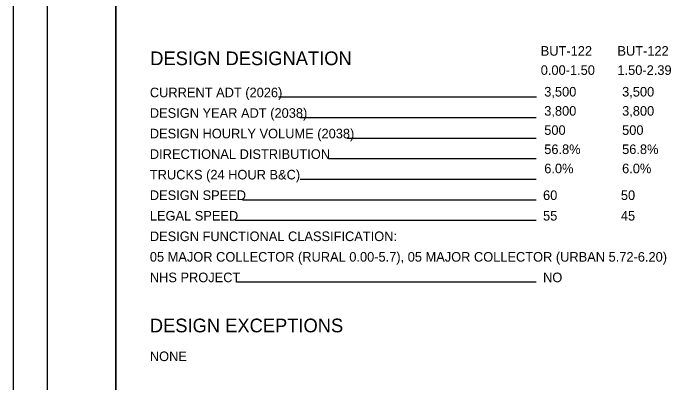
# Model space of a CAD drawing. Extents: x -11.1 to 43.5, y 0 to 22.
# Drawn here: x 0 to 9.7, y 5.64 to 11.03 of the extents above; entities that cross this region are included whole.
import ezdxf

# ---------------------------------------------------------------- set-up
doc = ezdxf.new("R2010")
doc.units = 0
for name, color, linetype in [('SH_Border', 7, 'Continuous'), ('SH_Cut_Line', 7, 'Continuous'), ('SH_Data', 7, 'Continuous'), ('SH_Text', 7, 'Continuous')]:
    doc.layers.add(name, color=color, linetype=linetype)

msp = doc.modelspace()

# ---------------------------------------------------------------- linework, layer by layer
at = {"layer": 'SH_Border'}
for points in [[(0.5, 21.5), (1.5, 21.5), (1.5, 0.5), (0.5, 0.5)], [(1.5, 21.5), (33.5, 21.5), (33.5, 0.5), (1.5, 0.5)]]:
    msp.add_lwpolyline(points, close=True, dxfattribs=at)
at = {"layer": 'SH_Cut_Line'}
msp.add_lwpolyline([(0, 0), (34, 0), (34, 22), (0, 22)], close=True, dxfattribs=at)
at = {"layer": 'SH_Data'}
for p, q in [((7.6424, 9.8062), (3.871, 9.8062)), ((7.6368, 9.5062), (4.1885, 9.5062)), ((7.6368, 9.2062), (4.8723, 9.2062)), ((7.6368, 8.9062), (4.6037, 8.9062)), ((7.6368, 8.6062), (4.1885, 8.6062)), ((7.6368, 8.3062), (3.346, 8.3062)), ((7.6368, 8.0062), (3.2422, 8.0062)), ((7.6368, 7.1062), (3.2669, 7.1062))]:
    msp.add_line(p, q, dxfattribs=at)

# ---------------------------------------------------------------- texts
msp.add_text('DESIGN DESIGNATION', height=0.2, dxfattribs=at).set_placement((2, 10.2747))
at = {"layer": 'SH_Text'}
for s, height, p in [('BUT-122', 0.14, (7.703, 10.4128)), ('BUT-122', 0.14, (8.823, 10.4128)), ('0.00-1.50', 0.14, (7.703, 10.1328)), ('1.50-2.39', 0.14, (8.823, 10.1328)), ('CURRENT ADT (2026)', 0.14, (1.9944, 9.8062)), ('3,500', 0.14, (7.7542, 9.8169)), ('3,500', 0.14, (8.8914, 9.8169)), ('DESIGN YEAR ADT (2038)', 0.14, (1.9944, 9.5062)), ('3,800', 0.14, (7.7542, 9.5369)), ('3,800', 0.14, (8.8914, 9.5369)), ('DESIGN HOURLY VOLUME (2038)', 0.14, (1.9944, 9.2062)), ('500', 0.14, (7.7542, 9.2569)), ('500', 0.14, (8.8914, 9.2569)), ('DIRECTIONAL DISTRIBUTION', 0.14, (1.9944, 8.9062)), ('56.8%', 0.14, (7.7542, 8.9769)), ('56.8%', 0.14, (8.8914, 8.9769)), ('6.0%', 0.14, (7.7542, 8.6969)), ('6.0%', 0.14, (8.8914, 8.6969)), ('TRUCKS (24 HOUR B&C)', 0.14, (1.9944, 8.6062)), ('DESIGN SPEED', 0.14, (1.9944, 8.3062)), ('60', 0.14, (7.7368, 8.3062)), ('50', 0.14, (8.8735, 8.3062)), ('LEGAL SPEED', 0.14, (1.9944, 8.0062)), ('55', 0.14, (7.7368, 8.0062)), ('45', 0.14, (8.8735, 8.0062)), ('DESIGN FUNCTIONAL CLASSIFICATION:', 0.14, (1.9944, 7.7062)), ('05 MAJOR COLLECTOR (RURAL 0.00-5.7), 05 MAJOR COLLECTOR (URBAN 5.72-6.20)', 0.14, (1.9944, 7.4062)), ('NHS PROJECT', 0.14, (1.9944, 7.1062)), ('NO', 0.14, (7.7368, 7.1062)), ('DESIGN EXCEPTIONS', 0.2, (1.9944, 6.3744)), ('NONE', 0.14, (1.9944, 5.9544))]:
    msp.add_text(s, height=height, dxfattribs=at).set_placement(p)

doc.saveas('drawing.dxf')
